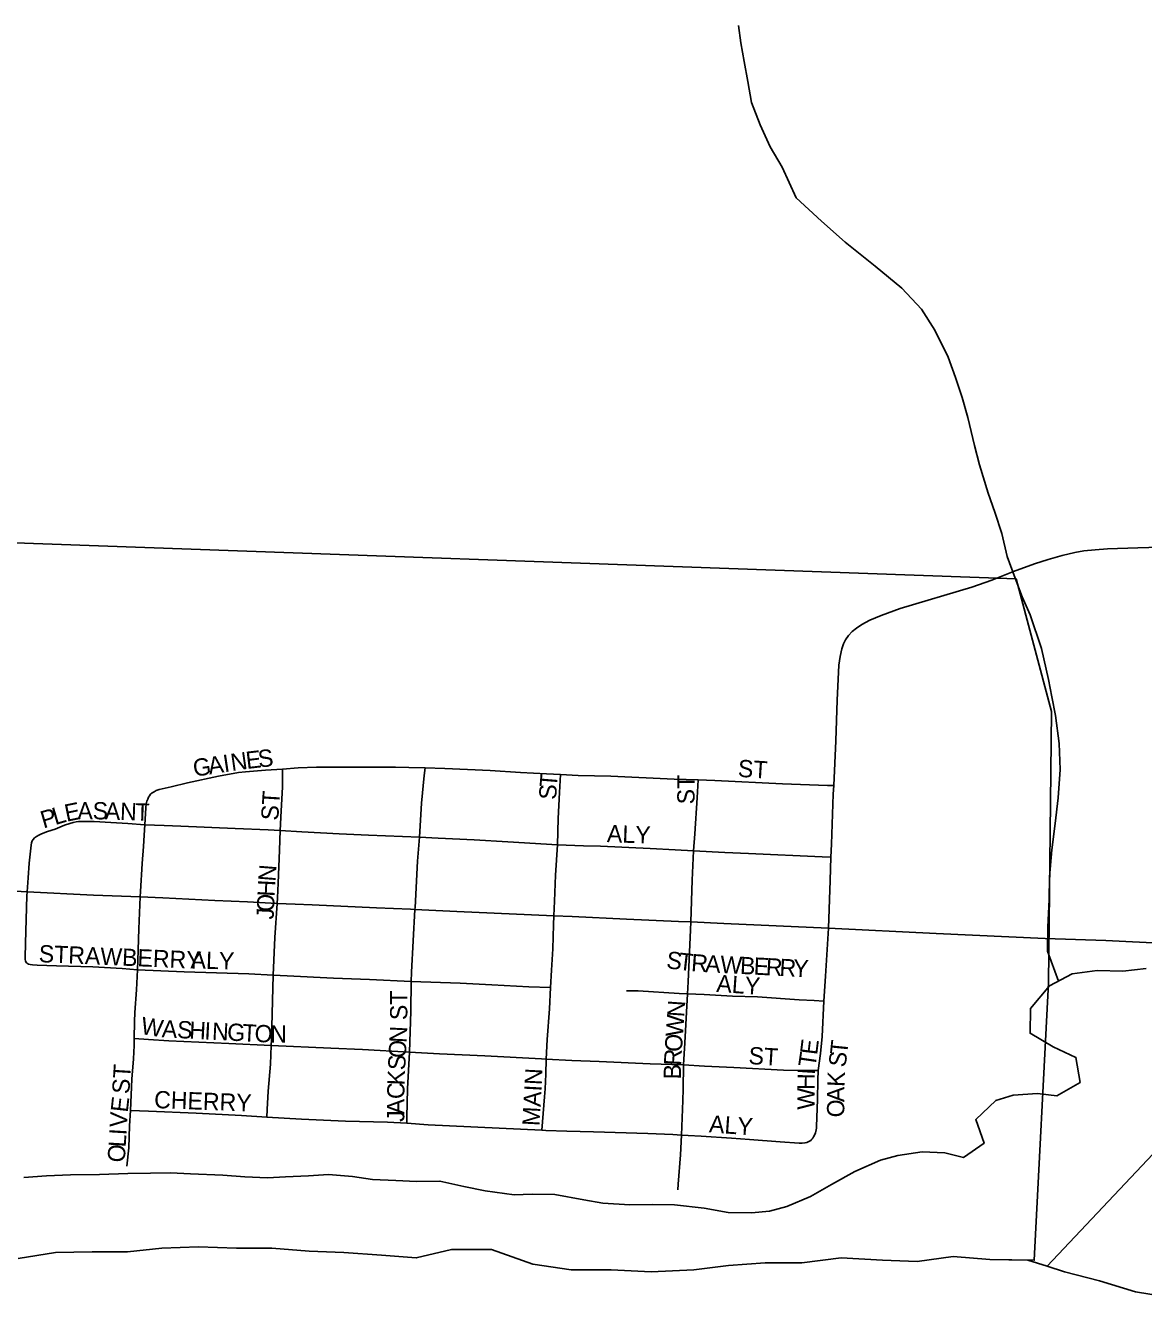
# Model space of a CAD drawing. Extents: x 1451455 to 1749751, y 218250 to 574981.
# Drawn here: x 1549049 to 1552286, y 290028 to 293717 of the extents above; entities that cross this region are included whole.
import ezdxf

# ---------------------------------------------------------------- set-up
doc = ezdxf.new("R2010")
doc.units = 0
for name, color, linetype in [('GM_X_City_Street', 7, 'Continuous'), ('GM_X_City_Street_Text', 7, 'Continuous'), ('GM_X_Corporation', 7, 'Continuous'), ('GM_X_County', 7, 'Continuous'), ('GM_X_Major_River', 7, 'Continuous'), ('GM_X_Minor_River', 7, 'Continuous'), ('GM_X_State_Route', 7, 'Continuous'), ('GM_X_Township', 7, 'Continuous'), ('GM_X_US_Route', 7, 'Continuous')]:
    doc.layers.add(name, color=color, linetype=linetype)

msp = doc.modelspace()

# ---------------------------------------------------------------- linework, layer by layer
at = {"layer": 'GM_X_City_Street'}
for points in [[(1549407.7, 291486.3), (1549411.1, 291490.7), (1549415.8, 291494.4), (1549421, 291497.8), (1549427, 291501), (1549435.7, 291504.4), (1549470.4, 291512.5), (1549518.2, 291524), (1549608, 291543.4), (1549666, 291553.2), (1549685.4, 291555.7), (1549744.1, 291560.1), (1549792.6, 291563.5)], [(1549785.8, 291386), (1549789.4, 291442.3), (1549792.7, 291511), (1549792.6, 291540.3), (1549792.6, 291563.5)], [(1549792.6, 291563.5), (1549838.6, 291567), (1549891, 291568.7), (1550035.2, 291569.3), (1550120.2, 291568.7), (1550159.1, 291568.2), (1550205.8, 291566.9)], [(1550190.1, 291365.9), (1550195.7, 291464.7), (1550203.6, 291544.6), (1550205.8, 291566.9)], [(1550205.8, 291566.9), (1550263.1, 291565.4), (1550394, 291559.4), (1550482.3, 291554), (1550557.6, 291550), (1550598.1, 291547.7)], [(1550588.8, 291344.4), (1550591.6, 291420.3), (1550595.4, 291495.6), (1550598.1, 291547.7)], [(1550598.1, 291547.7), (1550649.2, 291544.9), (1550744.1, 291542.6), (1550926.8, 291534.6), (1550996.8, 291532)], [(1550983.4, 291326.9), (1550987.1, 291376), (1550993.6, 291480.5), (1550996.8, 291532)], [(1550996.8, 291532), (1551044.5, 291530.2), (1551240.9, 291520.7), (1551370.9, 291516.2), (1551389.1, 291515.5)], [(1549394.3, 291402), (1549396.9, 291451.3), (1549398.4, 291462.9), (1549400.6, 291470.9), (1549402.7, 291476.7), (1549405.4, 291482.6), (1549407.7, 291486.3)], [(1549071, 291360), (1549075.2, 291364.4), (1549080.2, 291368), (1549087, 291372.3), (1549095.6, 291376.3), (1549112.1, 291382.5), (1549134.6, 291389.9), (1549161.9, 291400.8), (1549177.3, 291406), (1549186.4, 291408.4), (1549195.8, 291410.4), (1549202.6, 291411.5), (1549211.2, 291412), (1549228.6, 291412.1), (1549248, 291411.7), (1549263.6, 291410.8), (1549279.8, 291410.2), (1549345.1, 291405.6), (1549394.3, 291402)], [(1549380.8, 291193.4), (1549381.5, 291208.7), (1549387, 291290.2), (1549390.2, 291339.1), (1549392.1, 291371.7), (1549394.3, 291402)], [(1549394.3, 291402), (1549449.9, 291400.1), (1549499, 291398.1), (1549656.2, 291391.7), (1549751.1, 291387.7), (1549785.8, 291386)], [(1549777.2, 291174.6), (1549778.3, 291190.3), (1549780.4, 291232.8), (1549784, 291329.1), (1549785.8, 291386)], [(1549785.8, 291386), (1549848.7, 291381.6), (1549956.6, 291376.4), (1550041.7, 291372), (1550190.1, 291365.9)], [(1549053.8, 291208.3), (1549056.1, 291248.5), (1549059.8, 291290.8), (1549064.8, 291342.7), (1549066.1, 291349.7), (1549068.2, 291355.4), (1549071, 291360)], [(1550176.4, 291157.2), (1550176.7, 291162.2), (1550183.8, 291296.6), (1550190.1, 291365.9)], [(1550190.1, 291365.9), (1550244, 291363.4), (1550347.6, 291358.4), (1550445.7, 291352.5), (1550588.8, 291344.4)], [(1550578.8, 291138.8), (1550580.6, 291180.9), (1550583.6, 291256.4), (1550588.8, 291344.4)], [(1550588.8, 291344.4), (1550664.9, 291341.6), (1550713.9, 291339.9), (1550857.8, 291333.5), (1550929.7, 291329.8), (1550983.4, 291326.9)], [(1550975, 291120.7), (1550979.6, 291241.9), (1550983.4, 291326.9)], [(1550983.4, 291326.9), (1551073.5, 291322.1), (1551142.3, 291318.7), (1551355.2, 291309.6), (1551381, 291308.4)], [(1549050.1, 291004.9), (1549048.7, 291007.8), (1549047.8, 291011.9), (1549047.4, 291017.7), (1549049, 291059.2), (1549050.7, 291127.8), (1549053.1, 291196.3), (1549053.8, 291208.3)], [(1549372.8, 290982.4), (1549373.7, 291009), (1549376.5, 291100.7), (1549380.8, 291193.4)], [(1549766, 290967.1), (1549770.7, 291075.8), (1549777.2, 291174.6)], [(1550165.5, 290948.8), (1550166.8, 290975.2), (1550176.4, 291157.2)], [(1550569, 290931.4), (1550571.7, 290980.9), (1550575.7, 291043.2), (1550577.7, 291112), (1550578.8, 291138.8)], [(1550965.8, 290912.4), (1550967.2, 290947.2), (1550974.2, 291097.8), (1550975, 291120.7)], [(1551360.9, 290891.6), (1551365.4, 290963.6), (1551370.2, 291040.9), (1551373.7, 291102.5)], [(1549050.1, 291004.9), (1549051.9, 291002.3), (1549054.4, 291000.4), (1549057.9, 290998.9), (1549062.2, 290997.7), (1549069.3, 290996.5), (1549082.9, 290995.6), (1549138.5, 290993.8), (1549243.4, 290991.1), (1549328.5, 290986.4), (1549372.8, 290982.4)], [(1549363.8, 290783.3), (1549364.4, 290832.3), (1549365.4, 290858.4), (1549370.6, 290923.8), (1549372.8, 290982.4)], [(1549372.8, 290982.4), (1549508.3, 290975.9), (1549695, 290970.6), (1549766, 290967.1)], [(1549760.5, 290763.3), (1549761.4, 290780.8), (1549766, 290967.1)], [(1549766, 290967.1), (1549806.1, 290965.1), (1549940.4, 290958.5), (1550045.3, 290954.3), (1550165.5, 290948.8)], [(1550160.3, 290744.2), (1550164.8, 290862.1), (1550165.5, 290948.8)], [(1550165.5, 290948.8), (1550307, 290943.5), (1550398.7, 290939.1), (1550506.7, 290933.4), (1550569, 290931.4)], [(1550556.7, 290723.6), (1550559.7, 290780.9), (1550565.7, 290869.4), (1550569, 290931.4)], [(1550788.6, 290921.3), (1550822.4, 290921.5), (1550941.8, 290913.4), (1550965.8, 290912.4)], [(1550954, 290706.8), (1550957.8, 290770.5), (1550965.8, 290912.4)], [(1550965.8, 290912.4), (1551013.9, 290910.3), (1551095.9, 290906.3), (1551168.1, 290903.6), (1551289.4, 290895.6), (1551332, 290893.2), (1551360.9, 290891.6)], [(1551344.1, 290690.7), (1551350.5, 290740.3), (1551355.5, 290789.2), (1551360.9, 290891.6)], [(1549353.1, 290575.2), (1549356.6, 290665.4), (1549361.3, 290724.2), (1549363.5, 290763.5), (1549363.8, 290783.3)], [(1549363.8, 290783.3), (1549405.3, 290780.6), (1549464.1, 290776.8), (1549637.9, 290769.1), (1549760.5, 290763.3)], [(1549747.2, 290555.7), (1549748.5, 290578), (1549751.5, 290630.4), (1549758, 290708.8), (1549760.5, 290763.3)], [(1549760.5, 290763.3), (1549932.9, 290755.2), (1550024.7, 290751.3), (1550160.3, 290744.2)], [(1550152.6, 290537.7), (1550153, 290556), (1550154.8, 290637.3), (1550160.3, 290744.2)], [(1550160.3, 290744.2), (1550247.5, 290738.7), (1550378.7, 290733.3), (1550542.5, 290724.3), (1550556.7, 290723.6)], [(1550543.7, 290517.6), (1550547.9, 290565.8), (1550552.1, 290614.6), (1550553.6, 290637.4), (1550555.6, 290679.8), (1550556.7, 290723.6)], [(1550556.7, 290723.6), (1550631, 290720.1), (1550709.7, 290716.3), (1550857.2, 290710), (1550952.3, 290706.8), (1550954, 290706.8)], [(1550948.3, 290503.7), (1550952.2, 290603.7), (1550953.2, 290636.5), (1550954, 290706.8)], [(1550954, 290706.8), (1551014.5, 290703.7), (1551099.8, 290699.8), (1551243.6, 290691.6), (1551304.4, 290691.1), (1551344.1, 290690.7)], [(1551328.4, 290494.9), (1551330.9, 290498.8), (1551334.4, 290504.9), (1551336.4, 290510.3), (1551338.2, 290518.5), (1551339.3, 290524), (1551339.6, 290528.4), (1551342.6, 290606.5), (1551343.2, 290663), (1551344.1, 290690.7)], [(1549342.1, 290413.9), (1549347.7, 290467.2), (1549350.4, 290530.5), (1549353.1, 290575.2)], [(1549353.1, 290575.2), (1549405, 290573.1), (1549542.8, 290567.4), (1549673.9, 290559.9), (1549747.2, 290555.7)], [(1549747.2, 290555.7), (1549847.6, 290549.9), (1549975.5, 290544.4), (1550096.8, 290540.7), (1550152.6, 290537.7)], [(1550152.6, 290537.7), (1550214.5, 290533.7), (1550482.5, 290520.5), (1550543.7, 290517.6)], [(1550543.7, 290517.6), (1550555.1, 290517.1), (1550616, 290515.1), (1550693.7, 290512.7), (1550851.2, 290508.3), (1550923.2, 290505.4), (1550948.3, 290503.7)], [(1550938, 290345.3), (1550939.1, 290361.6), (1550945.2, 290446.6), (1550948.3, 290503.7)], [(1550948.3, 290503.7), (1550968, 290502.5), (1551005.7, 290500.2), (1551093.2, 290494.3), (1551145.5, 290490.6), (1551233.8, 290484.4), (1551289.3, 290480.5), (1551297.9, 290480.5), (1551305.6, 290481.2), (1551310.9, 290482.1), (1551315, 290483.8), (1551318.8, 290485.7), (1551322.4, 290488.2), (1551325.6, 290491.4), (1551328.4, 290494.9)]]:
    msp.add_lwpolyline(points, dxfattribs=at)
at = {"layer": 'GM_X_Corporation'}
msp.add_lwpolyline([(1548695.8, 292230.3), (1551917.2, 292113.9), (1552019.7, 291729.8), (1552010.9, 290944.6), (1551969.7, 290141.4), (1551840.9, 290143.8), (1551734.9, 290151.8), (1551630.8, 290137.8), (1551530.8, 290141.8), (1551410.7, 290147.8), (1551296.7, 290133.8), (1551190.6, 290133.8), (1551084.6, 290125.8), (1550984.5, 290113.8), (1550860.5, 290107.8), (1550744.4, 290113.8), (1550628.4, 290113.8), (1550518.3, 290129.8), (1550398.3, 290171.9), (1550282.2, 290171.9), (1550180.2, 290147.9), (1550080.1, 290155.9), (1549970.1, 290163.9), (1549870.1, 290167.9), (1549762, 290176), (1549660, 290176), (1549549.9, 290180), (1549443.9, 290176), (1549343.8, 290165.9), (1549241.8, 290165.9), (1549135.7, 290163.9), (1549027.7, 290145.9)], dxfattribs=at)
at = {"layer": 'GM_X_County'}
msp.add_lwpolyline([(1549027.7, 290145.9), (1549135.7, 290163.9), (1549241.8, 290165.9), (1549343.8, 290165.9), (1549443.9, 290176), (1549549.9, 290180), (1549660, 290176), (1549762, 290176), (1549870.1, 290167.9), (1549970.1, 290163.9), (1550080.1, 290155.9), (1550180.2, 290147.9), (1550282.2, 290171.9), (1550398.3, 290171.9), (1550518.3, 290129.8), (1550628.4, 290113.8), (1550744.4, 290113.8), (1550860.5, 290107.8), (1550984.5, 290113.8), (1551084.6, 290125.8), (1551190.6, 290133.8), (1551296.7, 290133.8), (1551410.7, 290147.8), (1551530.8, 290141.8), (1551630.8, 290137.8), (1551734.9, 290151.8), (1551840.9, 290143.8), (1551951, 290141.8), (1552007.3, 290123.7), (1552057, 290107.7), (1552159.1, 290081.6), (1552263.1, 290049.6), (1552399.2, 290027.5)], dxfattribs=at)
at = {"layer": 'GM_X_Major_River'}
for points in [[(1552293.7, 290985.6), (1552225.8, 290978.6), (1552152, 290979.8), (1552080, 290970.8), (1552013.6, 290935.8), (1551958.7, 290870.6), (1551957.6, 290798.6), (1552024.9, 290759.5), (1552090.3, 290728.5), (1552103.1, 290656.2), (1552034.7, 290617.2), (1551978.9, 290624.1), (1551909, 290619.2), (1551858.9, 290603.9), (1551800.2, 290548.8), (1551825.1, 290480.3), (1551764.6, 290439.2), (1551710.9, 290452), (1551645.1, 290455.1), (1551575, 290444.1), (1551524.9, 290430.9), (1551450.6, 290398), (1551382.2, 290361), (1551321.8, 290325.9), (1551253.5, 290296.9), (1551203.4, 290283.6), (1551151.4, 290278.5), (1551083.6, 290279.5), (1551013.9, 290292.5), (1550928.3, 290301.9), (1550864.4, 290302.8), (1550798.6, 290301.8), (1550720.8, 290307), (1550665.1, 290315.9)], [(1550665.1, 290315.9), (1550581.5, 290331.2), (1550515.6, 290332.2), (1550463.7, 290331), (1550380.1, 290342.3), (1550318.4, 290355.2), (1550248.8, 290370.3), (1550180.9, 290369.3), (1550121.1, 290372.2), (1550053.3, 290375.3), (1549995.5, 290384.2), (1549925.8, 290389.2), (1549867.8, 290386.1), (1549801.9, 290383.1), (1549750, 290379.9), (1549684.2, 290382.9), (1549620.4, 290387.9), (1549526.7, 290391.3), (1549468.8, 290394.2), (1549410.9, 290393.1), (1549345.1, 290392.1), (1549263.2, 290389.3), (1549179.4, 290388.6), (1549109.5, 290385.7), (1549043.5, 290380.6)]]:
    msp.add_lwpolyline(points, dxfattribs=at)
at = {"layer": 'GM_X_Minor_River'}
msp.add_lwpolyline([(1552039.6, 290949.6), (1552008.1, 291035.8), (1552009.3, 291105.8), (1552012.6, 291185.9), (1552013.7, 291251.9), (1552021, 291329.9), (1552030.2, 291405.9), (1552039.4, 291479.8), (1552044.8, 291561.8), (1552042, 291637.9), (1552031.4, 291718.2), (1552020.3, 291772.4), (1552011.1, 291822.6), (1551990.6, 291913), (1551958.3, 292009.7), (1551935.1, 292062.1), (1551914.1, 292116.5), (1551891.1, 292178.9), (1551876.2, 292245.2), (1551855.3, 292307.6), (1551836.2, 292362), (1551811.6, 292444.4), (1551796.5, 292500.7), (1551777.9, 292581.1), (1551760.8, 292639.4), (1551741.8, 292697.8), (1551720.8, 292756.2), (1551682.1, 292834.9), (1551643.2, 292895.6), (1551586.2, 292956.5), (1551509.3, 293019.8), (1551422.6, 293089.2), (1551353.6, 293150.4), (1551280.8, 293217.6), (1551240.3, 293306.3), (1551205.3, 293364.9), (1551176.4, 293429.4), (1551151.5, 293493.9), (1551140.5, 293554.1), (1551129.5, 293612.3), (1551120.4, 293666.5), (1551113.2, 293716.7)], dxfattribs=at)
at = {"layer": 'GM_X_State_Route'}
for points in [[(1551970.4, 292157.7), (1552009.6, 292170.3), (1552051, 292181.8), (1552087.6, 292190.7), (1552113.1, 292195.2), (1552145.9, 292198.5), (1552181.4, 292201.3), (1552269.7, 292203.8), (1552364.6, 292207.1), (1552489.1, 292213.2), (1552731.1, 292229.1), (1552786.7, 292233), (1552865.1, 292238.9), (1552891.5, 292243.2), (1552917.3, 292250.3), (1552933, 292257.2), (1552937.3, 292260.3)], [(1551373.7, 291102.5), (1551378.6, 291241.3), (1551381, 291308.4), (1551382.3, 291346.4), (1551387.8, 291490.6), (1551389.1, 291515.5), (1551395.5, 291644.8), (1551399, 291762.9), (1551404.2, 291864), (1551407.6, 291889.6), (1551412.5, 291911.4), (1551417.6, 291926.3), (1551423, 291937.4), (1551431.8, 291950.3), (1551442.4, 291961.8), (1551454.6, 291971.8), (1551470.7, 291982.2), (1551493.6, 291994.2), (1551526.4, 292008.3), (1551581.7, 292028.4), (1551789.2, 292090.7), (1551847.1, 292110.7), (1551910, 292135.6), (1551970.4, 292157.7)]]:
    msp.add_lwpolyline(points, dxfattribs=at)
at = {"layer": 'GM_X_Township'}
for points in [[(1552507.4, 290654.3), (1552007.3, 290123.7), (1551951, 290141.8), (1551840.9, 290143.8), (1551734.9, 290151.8), (1551630.8, 290137.8), (1551530.8, 290141.8), (1551410.7, 290147.8), (1551296.7, 290133.8), (1551190.6, 290133.8), (1551084.6, 290125.8), (1550984.5, 290113.8), (1550860.5, 290107.8), (1550744.4, 290113.8), (1550628.4, 290113.8), (1550518.3, 290129.8), (1550398.3, 290171.9), (1550282.2, 290171.9), (1550180.2, 290147.9), (1550080.1, 290155.9), (1549970.1, 290163.9), (1549870.1, 290167.9), (1549762, 290176), (1549660, 290176), (1549549.9, 290180), (1549443.9, 290176), (1549343.8, 290165.9), (1549241.8, 290165.9), (1549135.7, 290163.9), (1549027.7, 290145.9)], [(1552507.4, 290654.3), (1552007.3, 290123.7), (1552057, 290107.7), (1552159.1, 290081.6), (1552263.1, 290049.6), (1552399.2, 290027.5)]]:
    msp.add_lwpolyline(points, dxfattribs=at)
at = {"layer": 'GM_X_US_Route'}
for points in [[(1548880.8, 291217.2), (1548898.6, 291216.1), (1548983.8, 291211.8), (1549053.8, 291208.3), (1549246, 291198.8), (1549380.8, 291193.4), (1549446, 291190.8), (1549596.6, 291183.3), (1549691.7, 291179), (1549777.2, 291174.6), (1549829.2, 291171.9), (1549878.4, 291170), (1550064.9, 291162.1), (1550163.2, 291157.9), (1550176.4, 291157.2), (1550297.5, 291151), (1550513.9, 291141.7), (1550578.8, 291138.8), (1550631.8, 291136.4), (1550789.1, 291129), (1550939.7, 291122.4), (1550975, 291120.7), (1551070.8, 291116.3), (1551373.7, 291102.5)], [(1551373.7, 291102.5), (1551685.7, 291087.8), (1552001.8, 291073), (1552177, 291066.7)], [(1552177, 291066.7), (1552507.3, 291050.6)]]:
    msp.add_lwpolyline(points, dxfattribs=at)

# ---------------------------------------------------------------- texts
at = {"layer": 'GM_X_City_Street_Text'}
for s, rotation, p in [('G', 8.5891, (1549537.7, 291541.1)), ('A', 8.5927, (1549581.2, 291547.7)), ('I', 8.6057, (1549624.7, 291554.2)), ('N', 8.059, (1549646.3, 291557.5)), ('E', 6.6675, (1549689.6, 291563.6)), ('S', 6.3507, (1549724.5, 291567.7)), ('ST', 356.419, (1551110.5, 291541.2)), ('T', 85.2545, (1550587, 291508.7)), ('ST', 90, (1550986.1, 291461.4)), ('ST', 86.4254, (1549780.5, 291413.6)), ('S', 87.7454, (1550585.7, 291474.1)), ('P', 16.3263, (1549100.8, 291391.2)), ('L', 16.3339, (1549134.6, 291401.1)), ('E', 11.6234, (1549167.4, 291410.7)), ('A', 0.5027, (1549199.3, 291417.6)), ('S', 359.6175, (1549243.1, 291417.9)), ('A', 358.2183, (1549278, 291417.7)), ('N', 357.9121, (1549321.9, 291416.4)), ('T', 358.3921, (1549366.3, 291414.7)), ('ALY', 358.0261, (1550731.8, 291352)), ('N', 85.5585, (1549772.3, 291236.8)), ('H', 87.1245, (1549770.1, 291193.2)), ('O', 87.584, (1549768.2, 291149.3)), ('J', 87.5949, (1549767.3, 291127.4)), ('STRAWBERRY', 357.6136, (1549086.4, 291004.4)), ('ALY', 358.0262, (1549526.2, 290986.8)), ('S', 353.4019, (1550902.8, 290986.8)), ('T', 353.4146, (1550937.8, 290982.7)), ('R', 355.8433, (1550975.1, 290978.5)), ('A', 357.0936, (1551015.8, 290975.5)), ('W', 357.0818, (1551059.7, 290973.3)), ('B', 357.0879, (1551116.8, 290970.4)), ('E', 357.0892, (1551156.4, 290968.4)), ('R', 357.0842, (1551191.6, 290966.6)), ('R', 357.0842, (1551231.1, 290964.6)), ('Y', 357.1724, (1551270.7, 290962.6)), ('ALY', 356.0534, (1551048.3, 290918.5)), ('ST', 90, (1550154.5, 290836.6)), ('N', 86.0069, (1550956.2, 290844.1)), ('W', 350.8486, (1549380.4, 290796.9)), ('A', 356.874, (1549442.6, 290787.2)), ('S', 357.1633, (1549486.8, 290784.8)), ('H', 357.1612, (1549522, 290783)), ('I', 357.1572, (1549565.9, 290780.8)), ('N', 357.1572, (1549587.9, 290779.8)), ('G', 357.1572, (1549631.8, 290777.6)), ('T', 357.1633, (1549675.8, 290775.4)), ('O', 357.4595, (1549711.2, 290773.6)), ('N', 359.4128, (1549757, 290771.6)), ('W', 86.0036, (1550952.2, 290787.1)), ('N', 87.2014, (1550152.1, 290769.8)), ('O', 86.0296, (1550949.2, 290743.2)), ('E', 82.9298, (1551340.9, 290734.2)), ('O', 87.2062, (1550150, 290725.9)), ('R', 86.8168, (1550947, 290703.8)), ('ST', 356.4258, (1551141.3, 290709.6)), ('T', 81.6651, (1551335.7, 290698.2)), ('S', 82.1616, (1551423, 290698.3)), ('T', 84.2369, (1551428, 290735.1)), ('ST', 86.419, (1549349.3, 290621.6)), ('S', 87.1983, (1550148.2, 290690.7)), ('B', 89.2592, (1550946.5, 290664.8)), ('K', 87.5076, (1550146.3, 290646.8)), ('MAIN', 86.9854, (1550537.3, 290529)), ('H', 89.6214, (1551334.1, 290634.1)), ('I', 86.3037, (1551334.4, 290677.3)), ('K', 87.3652, (1551420, 290642.4)), ('CHERRY', 357.9538, (1549420.6, 290582)), ('C', 89.1742, (1550145.8, 290607.6)), ('W', 89.6133, (1551333.7, 290576.9)), ('A', 89.6612, (1551419.7, 290598.9)), ('E', 83.7307, (1549344.8, 290567.8)), ('A', 89.9454, (1550145.7, 290563.8)), ('O', 89.9891, (1551419.7, 290555)), ('V', 86.5552, (1549342.2, 290524.5)), ('J', 89.9563, (1550145.7, 290541.8)), ('ALY', 356.0571, (1551027, 290511.6)), ('L', 86.5557, (1549338.7, 290467.4)), ('I', 86.5618, (1549340.9, 290502.5)), ('O', 86.5661, (1549336.1, 290423.5))]:
    msp.add_text(s, height=50, rotation=rotation, dxfattribs=at).set_placement(p)

doc.saveas('drawing.dxf')
